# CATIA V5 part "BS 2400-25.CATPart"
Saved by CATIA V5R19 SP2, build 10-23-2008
Part number: BS 2400-25
Bounding box of the stored display mesh (mm): x -37.351 to 37.351, y -37.351 to 37.351, z 0 to 95
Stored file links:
  C:\Users\Bora\Desktop\3D Katı model\BS serisi\BS 2400\BS 2400-25.CATPart
  C:\Program Files\Dassault Systemes\B19\intel_a\reffiles\standard\MetricThickPitch.txt
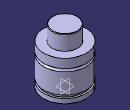
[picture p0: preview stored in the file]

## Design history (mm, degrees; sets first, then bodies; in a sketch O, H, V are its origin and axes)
Body1 (main body)
  Sketch1 on yz-plane, origin (0, 0, 0), H (0, 1, 0), V (0, 0, 1)
    point P1 (22.5, 94)
    point P3 (22.5, 94)
    point P7 (37.5, 53.5)
    point P9 (37.5, 53.5)
    point P10 (37.5, 48.5)
    point P14 (37.5, 48.5)
    line L1 (22.5, 94) -> (22.5, 69)
    arc A1 centre (21.5, 94) radius 1 from (22.5, 94) to (21.5, 95) ccw
    line L2 (37.5, 0) -> (37.5, 8)
    line L3 (37.5, 53.5) -> (37.5, 69)
    arc A2 centre (37.5, 51) radius 2.5 from (37.5, 53.5) to (37.5, 48.5) ccw
    line L4 (34.5, 13) -> (34.5, 8)
    line L5 (37.5, 13) -> (37.5, 48.5)
    line L6 (21.5, 95) -> (0, 95)
    point P15 (0, 95)
    line L7 (22.5, 69) -> (37.5, 69)
    line L8 (0, 0) -> (37.5, 0)
    line L9 (34.5, 13) -> (37.5, 13)
    line L10 (34.5, 8) -> (37.5, 8)
    coincidence: P15 V, P1 P3, P7 P9, P10 P14
    tangency: L6 A1
    horizontal: L7 H, L8 H, L9 H, L10 H
  Shaft1: profile Sketch1, axis Sketch1.V, angle 360
  Sketch2 on face of Shaft1 from Sketch1.L8, origin (0, 0, 0), H (1, 0, 0), V (0, -1, 0)
    point P1 (20, 0)
    distance P1 V = 20
  Hole1: placed by Sketch2, at (20, 0, 0) direction (0, 0, 1), diameter 6.647, depth 5, threaded "M8", thread diameter 8, thread depth 5, pitch 1.25
  CircPattern1: of Hole1, instances 4, angular step 90, axis from xy-plane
